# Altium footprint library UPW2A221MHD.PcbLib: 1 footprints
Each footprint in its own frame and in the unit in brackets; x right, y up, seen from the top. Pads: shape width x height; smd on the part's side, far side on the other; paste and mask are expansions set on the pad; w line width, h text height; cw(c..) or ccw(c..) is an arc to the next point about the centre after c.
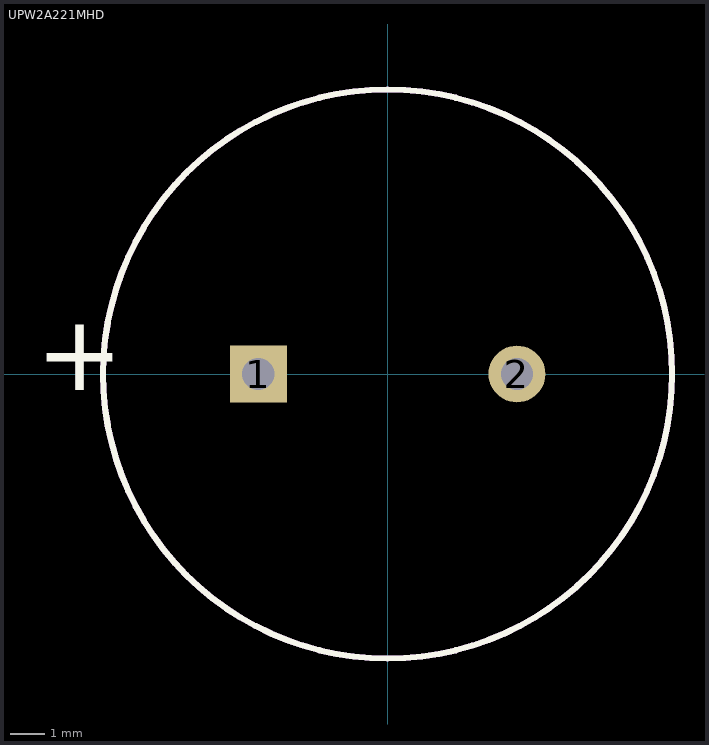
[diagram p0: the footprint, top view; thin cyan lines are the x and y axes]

## UPW2A221MHD [mil] "16Dx25T-7.5mm LS"
height 1062.99
pads (2):
  rect 65x65 hole 37: 1(-147.64,0)
  round 65 hole 37: 2(147.64,0)
Top Overlay:
  circle w7: c0,0 r324.8
  text "+" at -401.57,-47.24 h150
M5 Assembly Top:
  circle w7: c0,0 r324.8
  text ".Designator" at -165.35,-15.75 h72.83
  text "+" at -401.57,-47.24 h150
3D body: height 1062.99, standoff 0, extent -324.8,-324.8 324.81,324.81
3D body: height 1066.93, standoff 1062.99, extent 0.02,-324.78 324.78,324.78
